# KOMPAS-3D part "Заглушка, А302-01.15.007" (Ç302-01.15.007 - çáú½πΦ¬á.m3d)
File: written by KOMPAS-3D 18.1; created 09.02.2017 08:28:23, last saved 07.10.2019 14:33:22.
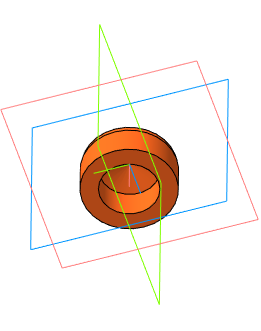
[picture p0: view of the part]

Document properties: Автор: Милов; Организация: Милов; Полное имя файла: D:\Мембранные насосы\Мембранный электропривод\А302-00.00.000 - ASTRA-302 (МЭ200)\3Д ПВХ\А302-01.15.007 - Заглушка.m3d

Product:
- Part/product: Заглушка  | designation А302-01.15.007
    Масса: 0.00113785
    Раздел спецификации: Детали
    Форматы листов документа: A4
    source file: А302-01.15.007 - Заглушка.cdw
- Part/product: Заглушка  | designation А302-03.15.007
    Масса: 0.00340597
    Раздел спецификации: Детали
    Форматы листов документа: A4
    source file: ..\Чертежи Полипропилен\А302-03.15.007 - Заглушка.cdw

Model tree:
1. Эскиз:7
2. Операция вращения:1
     Угол 1 = 360
3. Скругление:17  (with: Операция вращения:1)
     Радиус = 2
4. Скругление:18  (with: Операция вращения:1)
     Радиус = 4
5. Сечение поверхностью:1
6. Элемент выдавливания:1  (with: Операция вращения:1)
     Расстояние 2 = 6.5

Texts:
  Линейный размер с обрывом

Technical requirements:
  Gost Type A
